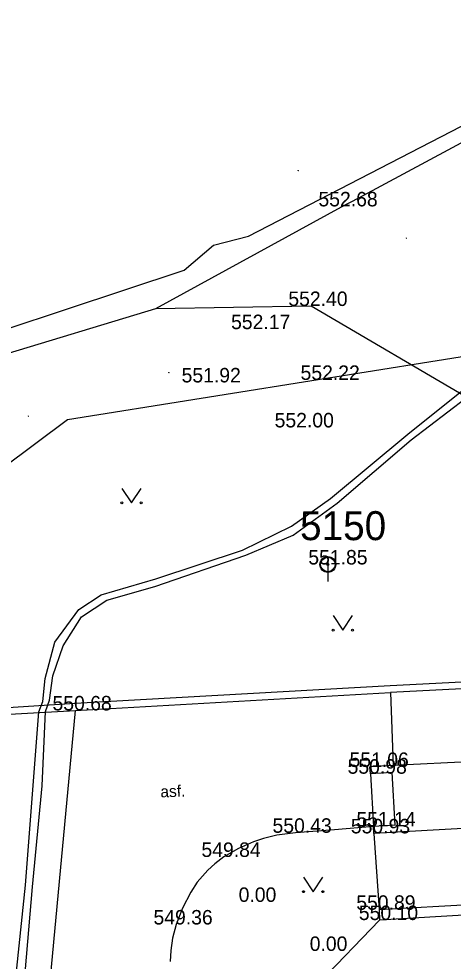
# Model space of a CAD drawing. Extents: x -669393 to -668650, y -1126925 to -1126294.
# Drawn here: x -669294.51 to -669272.02, y -1126483.77 to -1126434.96 of the extents above; entities that cross this region are included whole.
import ezdxf

# ---------------------------------------------------------------- set-up
doc = ezdxf.new("R2010")
doc.units = 0
for name, color, linetype in [('G_Bod_tecka', 7, 'Continuous'), ('G_Bod_vyska', 7, 'Continuous'), ('G_Bodove_pole', 7, 'Continuous'), ('G_Breh_Teren', 7, 'Continuous'), ('G_Budovy_Objekty', 7, 'Continuous'), ('G_Budovy_vstupy', 7, 'Continuous'), ('G_Plochy_zpevnene', 7, 'Continuous'), ('G_Ploty', 7, 'Continuous'), ('G_Ploty_vstupy', 7, 'Continuous'), ('G_Popisy_povrchu', 7, 'Continuous'), ('G_Site-kanalizace', 7, 'Continuous'), ('G_Vyskopis-bod_terenu', 7, 'Continuous'), ('G_Z_ELsilove_podz_kotovane', 7, 'Continuous'), ('G_Z_SPOJE_podz_geodeticky', 7, 'Continuous'), ('G_Z_SPOJE_podz_kotovane', 7, 'Continuous'), ('G_Z_SPOJE_podz_priblizne', 7, 'Continuous'), ('G_Zelen-Znacky', 7, 'Continuous')]:
    doc.layers.add(name, color=color, linetype=linetype)

msp = doc.modelspace()

# ---------------------------------------------------------------- linework, layer by layer
at = {"layer": 'G_Bod_tecka'}
for p, q in [((-669277.83, -1126444.67), (-669277.83, -1126444.67)), ((-669279.37, -1126449.83), (-669279.37, -1126449.83)), ((-669282.51, -1126451.03), (-669282.51, -1126451.03)), ((-669285.06, -1126453.79), (-669285.06, -1126453.79)), ((-669278.76, -1126453.66), (-669278.76, -1126453.66)), ((-669280.06, -1126456.12), (-669280.06, -1126456.12)), ((-669278.51, -1126463.22), (-669278.51, -1126463.22)), ((-669291.57, -1126470.78), (-669291.57, -1126470.78)), ((-669276.33, -1126473.71), (-669276.33, -1126473.71)), ((-669276.3, -1126474.06), (-669276.3, -1126474.06)), ((-669276.15, -1126476.79), (-669276.15, -1126476.79)), ((-669280.19, -1126477.12), (-669280.19, -1126477.12)), ((-669276.13, -1126477.15), (-669276.13, -1126477.15)), ((-669283.89, -1126478.37), (-669283.89, -1126478.37)), ((-669282.35, -1126480.7), (-669282.35, -1126480.7)), ((-669275.85, -1126481.11), (-669275.85, -1126481.11)), ((-669275.84, -1126481.64), (-669275.84, -1126481.64)), ((-669286.36, -1126481.87), (-669286.36, -1126481.87)), ((-669278.67, -1126483.24), (-669278.67, -1126483.24))]:
    msp.add_line(p, q, dxfattribs=at)
at = {"layer": 'G_Bodove_pole'}
for radius in [0.412, 0.05]:
    msp.add_circle((-669278.51, -1126463.22), radius, dxfattribs=at)
at = {"layer": 'G_Breh_Teren'}
for p, q in [((-669287.41, -1126449.96), (-669279.37, -1126449.83)), ((-669279.37, -1126449.83), (-669270.14, -1126455.25)), ((-669280.41, -1126486.39), (-669275.84, -1126481.64))]:
    msp.add_line(p, q, dxfattribs=at)
at = {"layer": 'G_Budovy_Objekty'}
for p, q in [((-669265.84, -1126473.16), (-669275.12, -1126473.64)), ((-669275.12, -1126473.64), (-669276.33, -1126473.71)), ((-669276.3, -1126474.06), (-669276.33, -1126473.71)), ((-669275.2, -1126474), (-669276.3, -1126474.06)), ((-669276.3, -1126474.06), (-669276.15, -1126476.79)), ((-669275.04, -1126476.73), (-669276.15, -1126476.79)), ((-669276.13, -1126477.15), (-669276.15, -1126476.79)), ((-669265.66, -1126476.58), (-669276.13, -1126477.15))]:
    msp.add_line(p, q, dxfattribs=at)
at = {"layer": 'G_Budovy_vstupy'}
msp.add_line((-669275.2, -1126474), (-669275.04, -1126476.73), dxfattribs=at)
at = {"layer": 'G_Plochy_zpevnene'}
for p, q in [((-669276.13, -1126477.15), (-669275.85, -1126481.11)), ((-669261.93, -1126480.31), (-669275.85, -1126481.11)), ((-669260.54, -1126480.73), (-669275.84, -1126481.64)), ((-669275.85, -1126481.11), (-669275.84, -1126481.64))]:
    msp.add_line(p, q, dxfattribs=at)
for points in [[(-669297.23, -1126526.98), (-669296.85, -1126522.54), (-669295.36, -1126509.24), (-669294.28, -1126498.88), (-669293.24, -1126488.52), (-669292.4, -1126479.65), (-669291.57, -1126470.78)], [(-669276.15, -1126476.79), (-669278.17, -1126476.96), (-669280.19, -1126477.12), (-669281.15, -1126477.25), (-669281.85, -1126477.42), (-669282.36, -1126477.59), (-669283.13, -1126477.93), (-669283.89, -1126478.37), (-669284.36, -1126478.72), (-669284.72, -1126479.05), (-669285.27, -1126479.68), (-669285.61, -1126480.2), (-669286.04, -1126481.02), (-669286.36, -1126481.87), (-669286.55, -1126482.57), (-669286.64, -1126483.21), (-669286.68, -1126483.78)]]:
    msp.add_lwpolyline(points, dxfattribs=at)
at = {"layer": 'G_Ploty'}
for p, q in [((-669276.9, -1126444.22), (-669266.05, -1126438.4)), ((-669287.41, -1126449.96), (-669277.81, -1126444.69)), ((-669301.06, -1126454.08), (-669287.41, -1126449.96)), ((-669266.03, -1126469.03), (-669275.29, -1126469.5)), ((-669275.29, -1126469.5), (-669291.59, -1126470.42)), ((-669267.86, -1126469.48), (-669275.27, -1126469.86)), ((-669291.57, -1126470.78), (-669275.27, -1126469.86)), ((-669291.59, -1126470.42), (-669299.85, -1126470.95)), ((-669299.84, -1126471.25), (-669291.57, -1126470.78))]:
    msp.add_line(p, q, dxfattribs=at)
at = {"layer": 'G_Ploty_vstupy'}
for p, q in [((-669277.81, -1126444.69), (-669276.9, -1126444.22)), ((-669275.27, -1126469.86), (-669275.12, -1126473.64))]:
    msp.add_line(p, q, dxfattribs=at)
at = {"layer": 'G_Site-kanalizace'}
msp.add_line((-669278.51, -1126462.845), (-669278.51, -1126464.095), dxfattribs=at)
msp.add_circle((-669278.51, -1126463.22), 0.375, dxfattribs=at)
at = {"layer": 'G_Vyskopis-bod_terenu'}
for p, q in [((-669280.05, -1126442.81), (-669280.03, -1126442.81)), ((-669280.04, -1126442.795), (-669280.04, -1126442.81)), ((-669280.04, -1126442.825), (-669280.04, -1126442.81)), ((-669274.46, -1126446.31), (-669274.44, -1126446.31)), ((-669274.45, -1126446.295), (-669274.45, -1126446.31)), ((-669274.45, -1126446.325), (-669274.45, -1126446.31)), ((-669287.42, -1126449.96), (-669287.4, -1126449.96)), ((-669287.41, -1126449.945), (-669287.41, -1126449.96)), ((-669287.41, -1126449.975), (-669287.41, -1126449.96)), ((-669286.75, -1126453.28), (-669286.73, -1126453.28)), ((-669286.74, -1126453.265), (-669286.74, -1126453.28)), ((-669286.74, -1126453.295), (-669286.74, -1126453.28)), ((-669294.03, -1126455.53), (-669294.01, -1126455.53)), ((-669294.02, -1126455.515), (-669294.02, -1126455.53)), ((-669294.02, -1126455.545), (-669294.02, -1126455.53))]:
    msp.add_line(p, q, dxfattribs=at)
at = {"layer": 'G_Z_ELsilove_podz_kotovane'}
for points in [[(-669294.703, -1126484.965), (-669294.159, -1126479.826), (-669293.773, -1126474.673), (-669293.472, -1126470.855), (-669293.268, -1126470.321), (-669293.146, -1126469.122), (-669292.654, -1126467.249), (-669291.4, -1126465.552), (-669290.24, -1126464.796), (-669287.41, -1126463.964), (-669282.924, -1126462.475), (-669280.401, -1126461.24), (-669278.377, -1126459.795), (-669274.375, -1126456.475), (-669270.731, -1126453.546), (-669269.236, -1126452.137), (-669267.198, -1126450.324), (-669265.586, -1126449.552), (-669261.964, -1126448.337), (-669257.103, -1126445.287), (-669256.5, -1126444.406), (-669255.97, -1126442.335), (-669256.127, -1126438.463), (-669256.083, -1126434.882)], [(-669294.238, -1126484.98), (-669293.805, -1126479.917), (-669293.311, -1126474.694), (-669293.134, -1126470.841), (-669292.916, -1126470.242), (-669292.754, -1126468.991), (-669292.213, -1126467.442), (-669291.269, -1126465.924), (-669289.953, -1126465.075), (-669287.478, -1126464.367), (-669282.756, -1126462.731), (-669280.311, -1126461.704), (-669278.03, -1126460.039), (-669274.204, -1126456.763), (-669270.394, -1126453.865), (-669269.061, -1126452.394), (-669267.07, -1126450.598), (-669265.489, -1126449.819), (-669261.844, -1126448.654), (-669256.767, -1126445.579), (-669255.918, -1126444.71), (-669255.346, -1126442.068), (-669255.801, -1126437.981), (-669255.665, -1126434.767)]]:
    msp.add_lwpolyline(points, dxfattribs=at)
at = {"layer": 'G_Z_SPOJE_podz_geodeticky'}
msp.add_lwpolyline([(-669263.78, -1126453.12), (-669264.3, -1126451.3), (-669291.99, -1126455.72), (-669300.48, -1126462.06), (-669302.48, -1126463.41), (-669301.93, -1126471.1)], dxfattribs=at)
at = {"layer": 'G_Z_SPOJE_podz_kotovane'}
for points in [[(-669301.38, -1126453.09), (-669285.95, -1126447.98), (-669284.44, -1126446.68), (-669282.62, -1126446.21), (-669270.56, -1126439.98), (-669262.2, -1126435.17), (-669260.95, -1126433.81), (-669259.64, -1126432.53), (-669259.88, -1126429.32), (-669259.99, -1126428.23), (-669259.52, -1126426.66), (-669259.651, -1126424.833)], [(-669263.78, -1126453.12), (-669264.3, -1126451.3), (-669291.99, -1126455.72), (-669300.48, -1126462.06), (-669302.48, -1126463.41), (-669301.93, -1126471.1)]]:
    msp.add_lwpolyline(points, dxfattribs=at)
at = {"layer": 'G_Z_SPOJE_podz_priblizne'}
msp.add_lwpolyline([(-669263.78, -1126453.12), (-669264.3, -1126451.3), (-669291.99, -1126455.72), (-669300.48, -1126462.06), (-669302.48, -1126463.41), (-669301.93, -1126471.1)], dxfattribs=at)
at = {"layer": 'G_Zelen-Znacky'}
for p, q in [((-669289.18, -1126459.28), (-669288.68, -1126460.03)), ((-669288.68, -1126460.03), (-669288.18, -1126459.28)), ((-669278.24, -1126465.87), (-669277.74, -1126466.62)), ((-669277.74, -1126466.62), (-669277.24, -1126465.87)), ((-669279.77, -1126479.42), (-669279.27, -1126480.17)), ((-669279.27, -1126480.17), (-669278.77, -1126479.42))]:
    msp.add_line(p, q, dxfattribs=at)
for centre in [(-669289.179, -1126460.031), (-669288.179, -1126460.031), (-669278.24, -1126466.62), (-669277.24, -1126466.62), (-669279.771, -1126480.17), (-669278.771, -1126480.17)]:
    msp.add_circle(centre, 0.05, dxfattribs=at)

# ---------------------------------------------------------------- texts
at = {"layer": 'G_Bod_vyska'}
for s, p in [('552.68', (-669278.998, -1126444.67)), ('552.40', (-669280.556, -1126449.83)), ('552.17', (-669283.522, -1126451.03)), ('552.22', (-669279.924, -1126453.66)), ('551.92', (-669286.084, -1126453.79)), ('552.00', (-669281.267, -1126456.12)), ('551.85', (-669279.522, -1126463.22)), ('550.68', (-669292.769, -1126470.78)), ('551.06', (-669277.388, -1126473.71)), ('550.98', (-669277.488, -1126474.06)), ('550.43', (-669281.376, -1126477.12)), ('550.93', (-669277.318, -1126477.15)), ('551.14', (-669277.031, -1126476.79)), ('549.84', (-669285.056, -1126478.37)), ('0.00', (-669283.13, -1126480.7)), ('550.89', (-669277.038, -1126481.11)), ('549.36', (-669287.54, -1126481.87)), ('550.10', (-669276.906, -1126481.64)), ('0.00', (-669279.45, -1126483.24))]:
    msp.add_text(s, height=0.75, dxfattribs=at).set_placement(p)
at = {"layer": 'G_Bodove_pole'}
msp.add_text('5150', height=1.5, dxfattribs=at).set_placement((-669279.952, -1126461.96))
at = {"layer": 'G_Popisy_povrchu'}
msp.add_text('asf.', height=0.6, rotation=2.1983, dxfattribs=at).set_placement((-669287.171, -1126475.29))

doc.saveas('drawing.dxf')
